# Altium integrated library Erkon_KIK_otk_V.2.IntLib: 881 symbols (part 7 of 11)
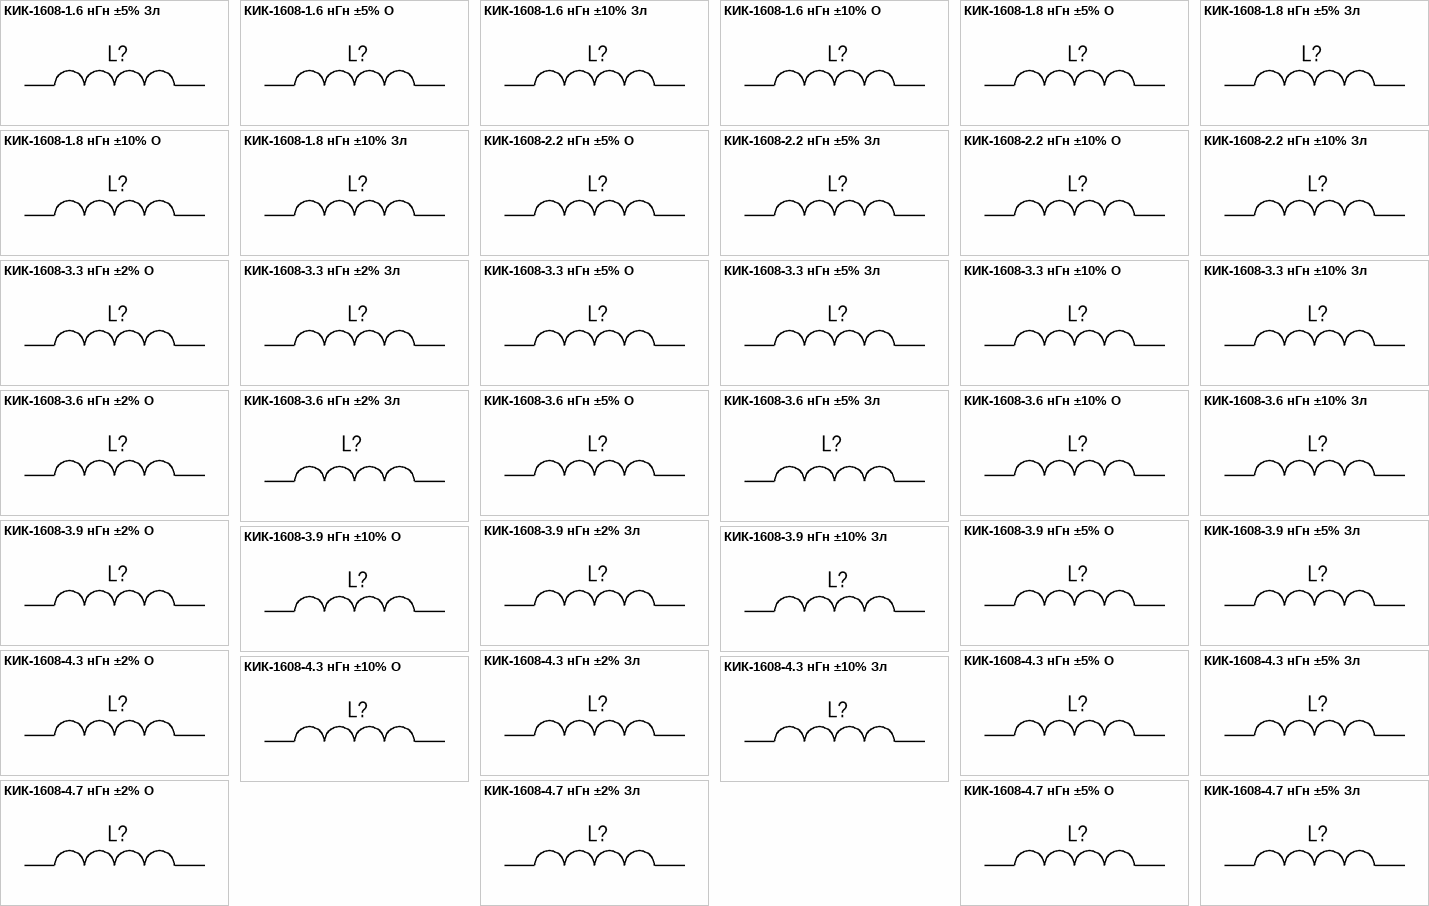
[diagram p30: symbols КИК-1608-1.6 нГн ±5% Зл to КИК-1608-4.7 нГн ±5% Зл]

## КИК-1608-3.9 нГн ±2% Зл
designator L?, comment 3.9 нГн ±2%  (value not drawn)
Катушка индуктивности с керамическим сердечником и золотым покрытием контактных площадок; Номиналиная индуктивность: 3.9 нГн; Добротность, не менее: 16; Резонансная частота, не менее: 6.90 ГГц; Сопротивление обмотки постоянноми току, не более: 0.080 Ом; Допустимый ток обмотки: 700 мА; Диапазон рабочих температур: от -60 до +125 ℃; Упаковка: Катушка и лента; Типоразмер: 1608 (0603); Технология монтажа: SMT; Изготовитель: АО "НПО "ЭРКОН"
footprint КИК-1608_Зл (Катушка индуктивности с керамическим сердечником  типоразмер 1005(0402))
pins: 1, 2

## КИК-1608-3.9 нГн ±5% O
designator L?, comment 3.9 нГн ±5%  (value not drawn)
Катушка индуктивности с керамическим сердечником и  финишным покрытием контактных площадок оловом; Номиналиная индуктивность: 3.9 нГн; Добротность, не менее: 16; Резонансная частота, не менее: 6.90 ГГц; Сопротивление обмотки постоянноми току, не более: 0.080 Ом; Допустимый ток обмотки: 700 мА; Диапазон рабочих температур: от -60 до +125 ℃; Упаковка: Катушка и лента; Типоразмер: 1608 (0603); Технология монтажа: SMT; Изготовитель: АО "НПО "ЭРКОН"
footprint КИК-1608_О (Катушка индуктивности с керамическим сердечником  типоразмер 1005(0402))
pins: 1, 2

## КИК-1608-3.9 нГн ±5% Зл
designator L?, comment 3.9 нГн ±5%  (value not drawn)
Катушка индуктивности с керамическим сердечником и золотым покрытием контактных площадок; Номиналиная индуктивность: 3.9 нГн; Добротность, не менее: 16; Резонансная частота, не менее: 6.90 ГГц; Сопротивление обмотки постоянноми току, не более: 0.080 Ом; Допустимый ток обмотки: 700 мА; Диапазон рабочих температур: от -60 до +125 ℃; Упаковка: Катушка и лента; Типоразмер: 1608 (0603); Технология монтажа: SMT; Изготовитель: АО "НПО "ЭРКОН"
footprint КИК-1608_Зл (Катушка индуктивности с керамическим сердечником  типоразмер 1005(0402))
pins: 1, 2

## КИК-1608-3.9 нГн ±10% O
designator L?, comment 3.9 нГн ±10%  (value not drawn)
Катушка индуктивности с керамическим сердечником и  финишным покрытием контактных площадок оловом; Номиналиная индуктивность: 3.9 нГн; Добротность, не менее: 16; Резонансная частота, не менее: 6.90 ГГц; Сопротивление обмотки постоянноми току, не более: 0.080 Ом; Допустимый ток обмотки: 700 мА; Диапазон рабочих температур: от -60 до +125 ℃; Упаковка: Катушка и лента; Типоразмер: 1608 (0603); Технология монтажа: SMT; Изготовитель: АО "НПО "ЭРКОН"
footprint КИК-1608_О (Катушка индуктивности с керамическим сердечником  типоразмер 1005(0402))
pins: 1, 2

## КИК-1608-3.9 нГн ±10% Зл
designator L?, comment 3.9 нГн ±10%  (value not drawn)
Катушка индуктивности с керамическим сердечником и золотым покрытием контактных площадок; Номиналиная индуктивность: 3.9 нГн; Добротность, не менее: 16; Резонансная частота, не менее: 6.90 ГГц; Сопротивление обмотки постоянноми току, не более: 0.080 Ом; Допустимый ток обмотки: 700 мА; Диапазон рабочих температур: от -60 до +125 ℃; Упаковка: Катушка и лента; Типоразмер: 1608 (0603); Технология монтажа: SMT; Изготовитель: АО "НПО "ЭРКОН"
footprint КИК-1608_Зл (Катушка индуктивности с керамическим сердечником  типоразмер 1005(0402))
pins: 1, 2

## КИК-1608-4.3 нГн ±2% O
designator L?, comment 4.3 нГн ±2%  (value not drawn)
Катушка индуктивности с керамическим сердечником и  финишным покрытием контактных площадок оловом; Номиналиная индуктивность: 4.3 нГн; Допускаемое отклонение индуктивности: ±5%; Добротность, не менее: 16; Резонансная частота, не менее: 5.90 ГГц; Сопротивление обмотки постоянноми току, не более: 0.080 Ом; Допустимый ток обмотки: 700 мА; Диапазон рабочих температур: от -60 до +125 ℃; Упаковка: Катушка и лента; Типоразмер: 1608 (0603); Технология монтажа: SMT; Изготовитель: АО "НПО "ЭРКОН"
footprint КИК-1608_О (Катушка индуктивности с керамическим сердечником  типоразмер 1005(0402))
pins: 1, 2

## КИК-1608-4.3 нГн ±2% Зл
designator L?, comment 4.3 нГн ±2%  (value not drawn)
Катушка индуктивности с керамическим сердечником и золотым покрытием контактных площадок; Номиналиная индуктивность: 4.3 нГн; Допускаемое отклонение индуктивности: ±5%; Добротность, не менее: 16; Резонансная частота, не менее: 5.90 ГГц; Сопротивление обмотки постоянноми току, не более: 0.080 Ом; Допустимый ток обмотки: 700 мА; Диапазон рабочих температур: от -60 до +125 ℃; Упаковка: Катушка и лента; Типоразмер: 1608 (0603); Технология монтажа: SMT; Изготовитель: АО "НПО "ЭРКОН"
footprint КИК-1608_Зл (Катушка индуктивности с керамическим сердечником  типоразмер 1005(0402))
pins: 1, 2

## КИК-1608-4.3 нГн ±5% O
designator L?, comment 4.3 нГн ±5%  (value not drawn)
Катушка индуктивности с керамическим сердечником и  финишным покрытием контактных площадок оловом; Номиналиная индуктивность: 4.3 нГн; Добротность, не менее: 16; Резонансная частота, не менее: 5.90 ГГц; Сопротивление обмотки постоянноми току, не более: 0.080 Ом; Допустимый ток обмотки: 700 мА; Диапазон рабочих температур: от -60 до +125 ℃; Упаковка: Катушка и лента; Типоразмер: 1608 (0603); Технология монтажа: SMT; Изготовитель: АО "НПО "ЭРКОН"
footprint КИК-1608_О (Катушка индуктивности с керамическим сердечником  типоразмер 1005(0402))
pins: 1, 2

## КИК-1608-4.3 нГн ±5% Зл
designator L?, comment 4.3 нГн ±5%  (value not drawn)
Катушка индуктивности с керамическим сердечником и золотым покрытием контактных площадок; Номиналиная индуктивность: 4.3 нГн; Добротность, не менее: 16; Резонансная частота, не менее: 5.90 ГГц; Сопротивление обмотки постоянноми току, не более: 0.080 Ом; Допустимый ток обмотки: 700 мА; Диапазон рабочих температур: от -60 до +125 ℃; Упаковка: Катушка и лента; Типоразмер: 1608 (0603); Технология монтажа: SMT; Изготовитель: АО "НПО "ЭРКОН"
footprint КИК-1608_Зл (Катушка индуктивности с керамическим сердечником  типоразмер 1005(0402))
pins: 1, 2

## КИК-1608-4.3 нГн ±10% O
designator L?, comment 4.3 нГн ±10%  (value not drawn)
Катушка индуктивности с керамическим сердечником и  финишным покрытием контактных площадок оловом; Номиналиная индуктивность: 4.3 нГн; Добротность, не менее: 16; Резонансная частота, не менее: 5.90 ГГц; Сопротивление обмотки постоянноми току, не более: 0.080 Ом; Допустимый ток обмотки: 700 мА; Диапазон рабочих температур: от -60 до +125 ℃; Упаковка: Катушка и лента; Типоразмер: 1608 (0603); Технология монтажа: SMT; Изготовитель: АО "НПО "ЭРКОН"
footprint КИК-1608_О (Катушка индуктивности с керамическим сердечником  типоразмер 1005(0402))
pins: 1, 2

## КИК-1608-4.3 нГн ±10% Зл
designator L?, comment 4.3 нГн ±10%  (value not drawn)
Катушка индуктивности с керамическим сердечником и золотым покрытием контактных площадок; Номиналиная индуктивность: 4.3 нГн; Добротность, не менее: 16; Резонансная частота, не менее: 5.90 ГГц; Сопротивление обмотки постоянноми току, не более: 0.080 Ом; Допустимый ток обмотки: 700 мА; Диапазон рабочих температур: от -60 до +125 ℃; Упаковка: Катушка и лента; Типоразмер: 1608 (0603); Технология монтажа: SMT; Изготовитель: АО "НПО "ЭРКОН"
footprint КИК-1608_Зл (Катушка индуктивности с керамическим сердечником  типоразмер 1005(0402))
pins: 1, 2

## КИК-1608-4.7 нГн ±2% O
designator L?, comment 4.7 нГн ±2%  (value not drawn)
Катушка индуктивности с керамическим сердечником и  финишным покрытием контактных площадок оловом; Номиналиная индуктивность: 4.7 нГн; Добротность, не менее: 16; Резонансная частота, не менее: 5.80 ГГц; Сопротивление обмотки постоянноми току, не более: 0.116 Ом; Допустимый ток обмотки: 700 мА; Диапазон рабочих температур: от -60 до +125 ℃; Упаковка: Катушка и лента; Типоразмер: 1608 (0603); Технология монтажа: SMT; Изготовитель: АО "НПО "ЭРКОН"
footprint КИК-1608_О (Катушка индуктивности с керамическим сердечником  типоразмер 1005(0402))
pins: 1, 2

## КИК-1608-4.7 нГн ±2% Зл
designator L?, comment 4.7 нГн ±2%  (value not drawn)
Катушка индуктивности с керамическим сердечником и золотым покрытием контактных площадок; Номиналиная индуктивность: 4.7 нГн; Добротность, не менее: 16; Резонансная частота, не менее: 5.80 ГГц; Сопротивление обмотки постоянноми току, не более: 0.116 Ом; Допустимый ток обмотки: 700 мА; Диапазон рабочих температур: от -60 до +125 ℃; Упаковка: Катушка и лента; Типоразмер: 1608 (0603); Технология монтажа: SMT; Изготовитель: АО "НПО "ЭРКОН"
footprint КИК-1608_Зл (Катушка индуктивности с керамическим сердечником  типоразмер 1005(0402))
pins: 1, 2

## КИК-1608-4.7 нГн ±5% O
designator L?, comment 4.7 нГн ±5%  (value not drawn)
Катушка индуктивности с керамическим сердечником и  финишным покрытием контактных площадок оловом; Номиналиная индуктивность: 4.7 нГн; Добротность, не менее: 16; Резонансная частота, не менее: 5.80 ГГц; Сопротивление обмотки постоянноми току, не более: 0.116 Ом; Допустимый ток обмотки: 700 мА; Диапазон рабочих температур: от -60 до +125 ℃; Упаковка: Катушка и лента; Типоразмер: 1608 (0603); Технология монтажа: SMT; Изготовитель: АО "НПО "ЭРКОН"
footprint КИК-1608_О (Катушка индуктивности с керамическим сердечником  типоразмер 1005(0402))
pins: 1, 2

## КИК-1608-4.7 нГн ±5% Зл
designator L?, comment 4.7 нГн ±5%  (value not drawn)
Катушка индуктивности с керамическим сердечником и золотым покрытием контактных площадок; Номиналиная индуктивность: 4.7 нГн; Добротность, не менее: 16; Резонансная частота, не менее: 5.80 ГГц; Сопротивление обмотки постоянноми току, не более: 0.116 Ом; Допустимый ток обмотки: 700 мА; Диапазон рабочих температур: от -60 до +125 ℃; Упаковка: Катушка и лента; Типоразмер: 1608 (0603); Технология монтажа: SMT; Изготовитель: АО "НПО "ЭРКОН"
footprint КИК-1608_Зл (Катушка индуктивности с керамическим сердечником  типоразмер 1005(0402))
pins: 1, 2

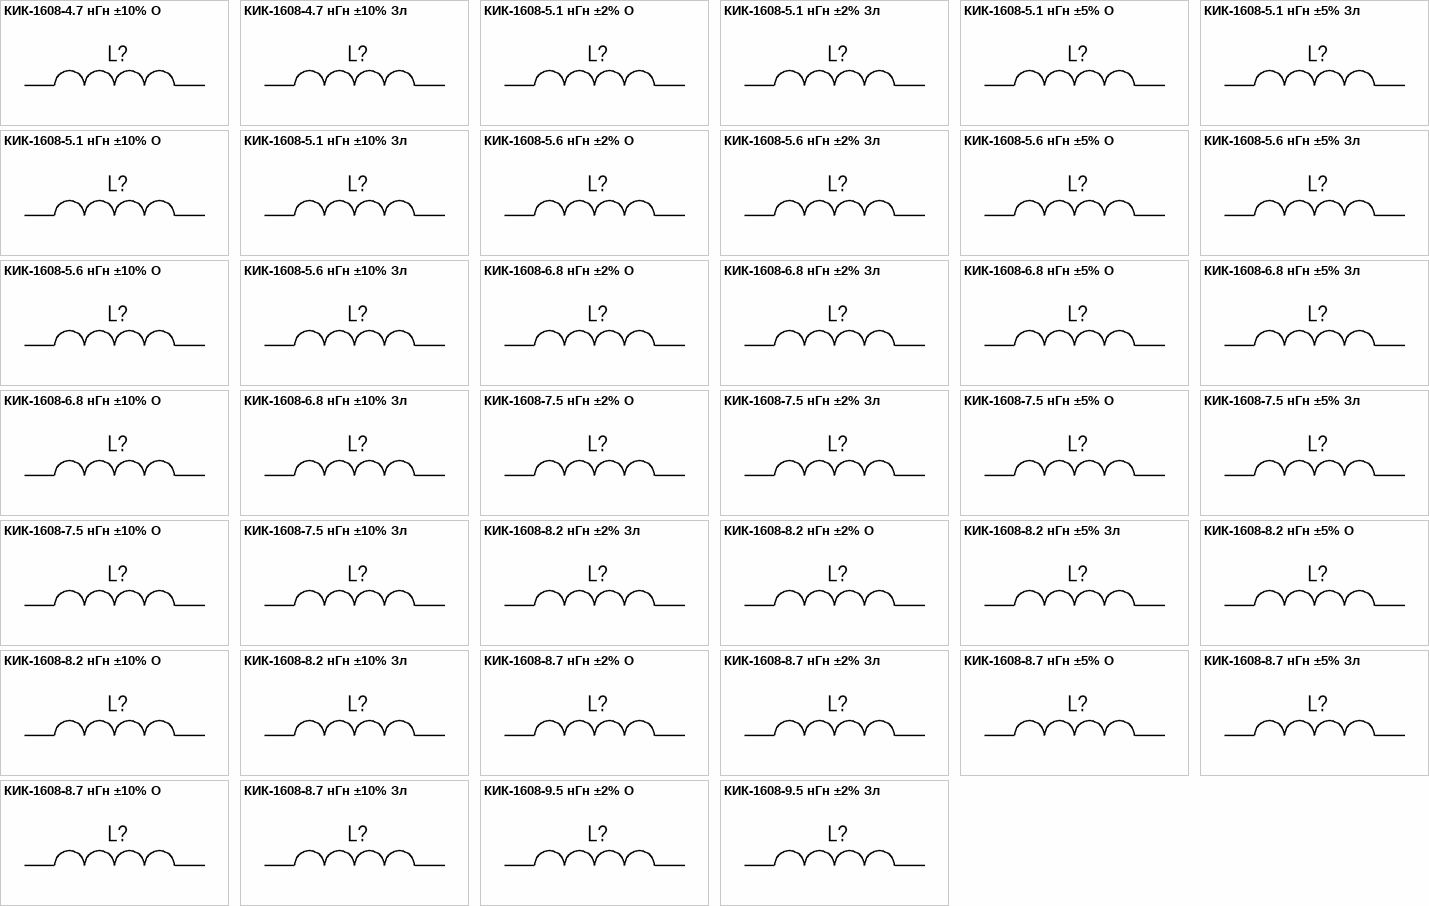
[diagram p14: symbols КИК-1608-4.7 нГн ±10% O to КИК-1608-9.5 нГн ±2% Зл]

## КИК-1608-4.7 нГн ±10% O
designator L?, comment 4.7 нГн ±10%  (value not drawn)
Катушка индуктивности с керамическим сердечником и  финишным покрытием контактных площадок оловом; Номиналиная индуктивность: 4.7 нГн; Добротность, не менее: 16; Резонансная частота, не менее: 5.80 ГГц; Сопротивление обмотки постоянноми току, не более: 0.116 Ом; Допустимый ток обмотки: 700 мА; Диапазон рабочих температур: от -60 до +125 ℃; Упаковка: Катушка и лента; Типоразмер: 1608 (0603); Технология монтажа: SMT; Изготовитель: АО "НПО "ЭРКОН"
footprint КИК-1608_О (Катушка индуктивности с керамическим сердечником  типоразмер 1005(0402))
pins: 1, 2

## КИК-1608-4.7 нГн ±10% Зл
designator L?, comment 4.7 нГн ±10%  (value not drawn)
Катушка индуктивности с керамическим сердечником и золотым покрытием контактных площадок; Номиналиная индуктивность: 4.7 нГн; Добротность, не менее: 16; Резонансная частота, не менее: 5.80 ГГц; Сопротивление обмотки постоянноми току, не более: 0.116 Ом; Допустимый ток обмотки: 700 мА; Диапазон рабочих температур: от -60 до +125 ℃; Упаковка: Катушка и лента; Типоразмер: 1608 (0603); Технология монтажа: SMT; Изготовитель: АО "НПО "ЭРКОН"
footprint КИК-1608_Зл (Катушка индуктивности с керамическим сердечником  типоразмер 1005(0402))
pins: 1, 2

## КИК-1608-5.1 нГн ±2% O
designator L?, comment 5.1 нГн ±2%  (value not drawn)
Катушка индуктивности с керамическим сердечником и  финишным покрытием контактных площадок оловом; Номиналиная индуктивность: 5.1 нГн; Добротность, не менее: 16; Резонансная частота, не менее: 5.70 ГГц; Сопротивление обмотки постоянноми току, не более: 0.140 Ом; Допустимый ток обмотки: 700 мА; Диапазон рабочих температур: от -60 до +125 ℃; Упаковка: Катушка и лента; Типоразмер: 1608 (0603); Технология монтажа: SMT; Изготовитель: АО "НПО "ЭРКОН"
footprint КИК-1608_О (Катушка индуктивности с керамическим сердечником  типоразмер 1005(0402))
pins: 1, 2

## КИК-1608-5.1 нГн ±2% Зл
designator L?, comment 5.1 нГн ±2%  (value not drawn)
Катушка индуктивности с керамическим сердечником и золотым покрытием контактных площадок; Номиналиная индуктивность: 5.1 нГн; Добротность, не менее: 16; Резонансная частота, не менее: 5.70 ГГц; Сопротивление обмотки постоянноми току, не более: 0.140 Ом; Допустимый ток обмотки: 700 мА; Диапазон рабочих температур: от -60 до +125 ℃; Упаковка: Катушка и лента; Типоразмер: 1608 (0603); Технология монтажа: SMT; Изготовитель: АО "НПО "ЭРКОН"
footprint КИК-1608_Зл (Катушка индуктивности с керамическим сердечником  типоразмер 1005(0402))
pins: 1, 2

## КИК-1608-5.1 нГн ±5% O
designator L?, comment 5.1 нГн ±5%  (value not drawn)
Катушка индуктивности с керамическим сердечником и  финишным покрытием контактных площадок оловом; Номиналиная индуктивность: 5.1 нГн; Добротность, не менее: 16; Резонансная частота, не менее: 5.70 ГГц; Сопротивление обмотки постоянноми току, не более: 0.140 Ом; Допустимый ток обмотки: 700 мА; Диапазон рабочих температур: от -60 до +125 ℃; Упаковка: Катушка и лента; Типоразмер: 1608 (0603); Технология монтажа: SMT; Изготовитель: АО "НПО "ЭРКОН"
footprint КИК-1608_О (Катушка индуктивности с керамическим сердечником  типоразмер 1005(0402))
pins: 1, 2

## КИК-1608-5.1 нГн ±5% Зл
designator L?, comment 5.1 нГн ±5%  (value not drawn)
Катушка индуктивности с керамическим сердечником и золотым покрытием контактных площадок; Номиналиная индуктивность: 5.1 нГн; Добротность, не менее: 16; Резонансная частота, не менее: 5.70 ГГц; Сопротивление обмотки постоянноми току, не более: 0.140 Ом; Допустимый ток обмотки: 700 мА; Диапазон рабочих температур: от -60 до +125 ℃; Упаковка: Катушка и лента; Типоразмер: 1608 (0603); Технология монтажа: SMT; Изготовитель: АО "НПО "ЭРКОН"
footprint КИК-1608_Зл (Катушка индуктивности с керамическим сердечником  типоразмер 1005(0402))
pins: 1, 2

## КИК-1608-5.1 нГн ±10% O
designator L?, comment 5.1 нГн ±10%  (value not drawn)
Катушка индуктивности с керамическим сердечником и  финишным покрытием контактных площадок оловом; Номиналиная индуктивность: 5.1 нГн; Добротность, не менее: 16; Резонансная частота, не менее: 5.70 ГГц; Сопротивление обмотки постоянноми току, не более: 0.140 Ом; Допустимый ток обмотки: 700 мА; Диапазон рабочих температур: от -60 до +125 ℃; Упаковка: Катушка и лента; Типоразмер: 1608 (0603); Технология монтажа: SMT; Изготовитель: АО "НПО "ЭРКОН"
footprint КИК-1608_О (Катушка индуктивности с керамическим сердечником  типоразмер 1005(0402))
pins: 1, 2

## КИК-1608-5.1 нГн ±10% Зл
designator L?, comment 5.1 нГн ±10%  (value not drawn)
Катушка индуктивности с керамическим сердечником и золотым покрытием контактных площадок; Номиналиная индуктивность: 5.1 нГн; Добротность, не менее: 16; Резонансная частота, не менее: 5.70 ГГц; Сопротивление обмотки постоянноми току, не более: 0.140 Ом; Допустимый ток обмотки: 700 мА; Диапазон рабочих температур: от -60 до +125 ℃; Упаковка: Катушка и лента; Типоразмер: 1608 (0603); Технология монтажа: SMT; Изготовитель: АО "НПО "ЭРКОН"
footprint КИК-1608_Зл (Катушка индуктивности с керамическим сердечником  типоразмер 1005(0402))
pins: 1, 2

## КИК-1608-5.6 нГн ±2% O
designator L?, comment 5.6 нГн ±2%  (value not drawn)
Катушка индуктивности с керамическим сердечником и  финишным покрытием контактных площадок оловом; Номиналиная индуктивность: 5.6 нГн; Добротность, не менее: 25; Резонансная частота, не менее: 4.76 ГГц; Сопротивление обмотки постоянноми току, не более: 0.145 Ом; Допустимый ток обмотки: 700 мА; Диапазон рабочих температур: от -60 до +125 ℃; Упаковка: Катушка и лента; Типоразмер: 1608 (0603); Технология монтажа: SMT; Изготовитель: АО "НПО "ЭРКОН"
footprint КИК-1608_О (Катушка индуктивности с керамическим сердечником  типоразмер 1005(0402))
pins: 1, 2

## КИК-1608-5.6 нГн ±2% Зл
designator L?, comment 5.6 нГн ±2%  (value not drawn)
Катушка индуктивности с керамическим сердечником и золотым покрытием контактных площадок; Номиналиная индуктивность: 5.6 нГн; Добротность, не менее: 25; Резонансная частота, не менее: 4.76 ГГц; Сопротивление обмотки постоянноми току, не более: 0.145 Ом; Допустимый ток обмотки: 700 мА; Диапазон рабочих температур: от -60 до +125 ℃; Упаковка: Катушка и лента; Типоразмер: 1608 (0603); Технология монтажа: SMT; Изготовитель: АО "НПО "ЭРКОН"
footprint КИК-1608_Зл (Катушка индуктивности с керамическим сердечником  типоразмер 1005(0402))
pins: 1, 2

## КИК-1608-5.6 нГн ±5% O
designator L?, comment 5.6 нГн ±5%  (value not drawn)
Катушка индуктивности с керамическим сердечником и  финишным покрытием контактных площадок оловом; Номиналиная индуктивность: 5.6 нГн; Добротность, не менее: 25; Резонансная частота, не менее: 4.76 ГГц; Сопротивление обмотки постоянноми току, не более: 0.145 Ом; Допустимый ток обмотки: 700 мА; Диапазон рабочих температур: от -60 до +125 ℃; Упаковка: Катушка и лента; Типоразмер: 1608 (0603); Технология монтажа: SMT; Изготовитель: АО "НПО "ЭРКОН"
footprint КИК-1608_О (Катушка индуктивности с керамическим сердечником  типоразмер 1005(0402))
pins: 1, 2

## КИК-1608-5.6 нГн ±5% Зл
designator L?, comment 5.6 нГн ±5%  (value not drawn)
Катушка индуктивности с керамическим сердечником и золотым покрытием контактных площадок; Номиналиная индуктивность: 5.6 нГн; Добротность, не менее: 25; Резонансная частота, не менее: 4.76 ГГц; Сопротивление обмотки постоянноми току, не более: 0.145 Ом; Допустимый ток обмотки: 700 мА; Диапазон рабочих температур: от -60 до +125 ℃; Упаковка: Катушка и лента; Типоразмер: 1608 (0603); Технология монтажа: SMT; Изготовитель: АО "НПО "ЭРКОН"
footprint КИК-1608_Зл (Катушка индуктивности с керамическим сердечником  типоразмер 1005(0402))
pins: 1, 2

## КИК-1608-5.6 нГн ±10% O
designator L?, comment 5.6 нГн ±10%  (value not drawn)
Катушка индуктивности с керамическим сердечником и  финишным покрытием контактных площадок оловом; Номиналиная индуктивность: 5.6 нГн; Добротность, не менее: 25; Резонансная частота, не менее: 4.76 ГГц; Сопротивление обмотки постоянноми току, не более: 0.145 Ом; Допустимый ток обмотки: 700 мА; Диапазон рабочих температур: от -60 до +125 ℃; Упаковка: Катушка и лента; Типоразмер: 1608 (0603); Технология монтажа: SMT; Изготовитель: АО "НПО "ЭРКОН"
footprint КИК-1608_О (Катушка индуктивности с керамическим сердечником  типоразмер 1005(0402))
pins: 1, 2

## КИК-1608-5.6 нГн ±10% Зл
designator L?, comment 5.6 нГн ±10%  (value not drawn)
Катушка индуктивности с керамическим сердечником и золотым покрытием контактных площадок; Номиналиная индуктивность: 5.6 нГн; Добротность, не менее: 25; Резонансная частота, не менее: 4.76 ГГц; Сопротивление обмотки постоянноми току, не более: 0.145 Ом; Допустимый ток обмотки: 700 мА; Диапазон рабочих температур: от -60 до +125 ℃; Упаковка: Катушка и лента; Типоразмер: 1608 (0603); Технология монтажа: SMT; Изготовитель: АО "НПО "ЭРКОН"
footprint КИК-1608_Зл (Катушка индуктивности с керамическим сердечником  типоразмер 1005(0402))
pins: 1, 2

## КИК-1608-6.8 нГн ±2% O
designator L?, comment 6.8 нГн ±2%  (value not drawn)
Катушка индуктивности с керамическим сердечником и  финишным покрытием контактных площадок оловом; Номиналиная индуктивность: 6.8 нГн; Добротность, не менее: 25; Резонансная частота, не менее: 5.80 ГГц; Сопротивление обмотки постоянноми току, не более: 0.110 Ом; Допустимый ток обмотки: 700 мА; Диапазон рабочих температур: от -60 до +125 ℃; Упаковка: Катушка и лента; Типоразмер: 1608 (0603); Технология монтажа: SMT; Изготовитель: АО "НПО "ЭРКОН"
footprint КИК-1608_О (Катушка индуктивности с керамическим сердечником  типоразмер 1005(0402))
pins: 1, 2

## КИК-1608-6.8 нГн ±2% Зл
designator L?, comment 6.8 нГн ±2%  (value not drawn)
Катушка индуктивности с керамическим сердечником и золотым покрытием контактных площадок; Номиналиная индуктивность: 6.8 нГн; Добротность, не менее: 25; Резонансная частота, не менее: 5.80 ГГц; Сопротивление обмотки постоянноми току, не более: 0.110 Ом; Допустимый ток обмотки: 700 мА; Диапазон рабочих температур: от -60 до +125 ℃; Упаковка: Катушка и лента; Типоразмер: 1608 (0603); Технология монтажа: SMT; Изготовитель: АО "НПО "ЭРКОН"
footprint КИК-1608_Зл (Катушка индуктивности с керамическим сердечником  типоразмер 1005(0402))
pins: 1, 2

## КИК-1608-6.8 нГн ±5% O
designator L?, comment 6.8 нГн ±5%  (value not drawn)
Катушка индуктивности с керамическим сердечником и  финишным покрытием контактных площадок оловом; Номиналиная индуктивность: 6.8 нГн; Добротность, не менее: 25; Резонансная частота, не менее: 5.80 ГГц; Сопротивление обмотки постоянноми току, не более: 0.110 Ом; Допустимый ток обмотки: 700 мА; Диапазон рабочих температур: от -60 до +125 ℃; Упаковка: Катушка и лента; Типоразмер: 1608 (0603); Технология монтажа: SMT; Изготовитель: АО "НПО "ЭРКОН"
footprint КИК-1608_О (Катушка индуктивности с керамическим сердечником  типоразмер 1005(0402))
pins: 1, 2

## КИК-1608-6.8 нГн ±5% Зл
designator L?, comment 6.8 нГн ±5%  (value not drawn)
Катушка индуктивности с керамическим сердечником и золотым покрытием контактных площадок; Номиналиная индуктивность: 6.8 нГн; Добротность, не менее: 25; Резонансная частота, не менее: 5.80 ГГц; Сопротивление обмотки постоянноми току, не более: 0.110 Ом; Допустимый ток обмотки: 700 мА; Диапазон рабочих температур: от -60 до +125 ℃; Упаковка: Катушка и лента; Типоразмер: 1608 (0603); Технология монтажа: SMT; Изготовитель: АО "НПО "ЭРКОН"
footprint КИК-1608_Зл (Катушка индуктивности с керамическим сердечником  типоразмер 1005(0402))
pins: 1, 2

## КИК-1608-6.8 нГн ±10% O
designator L?, comment 6.8 нГн ±10%  (value not drawn)
Катушка индуктивности с керамическим сердечником и  финишным покрытием контактных площадок оловом; Номиналиная индуктивность: 6.8 нГн; Добротность, не менее: 25; Резонансная частота, не менее: 5.80 ГГц; Сопротивление обмотки постоянноми току, не более: 0.110 Ом; Допустимый ток обмотки: 700 мА; Диапазон рабочих температур: от -60 до +125 ℃; Упаковка: Катушка и лента; Типоразмер: 1608 (0603); Технология монтажа: SMT; Изготовитель: АО "НПО "ЭРКОН"
footprint КИК-1608_О (Катушка индуктивности с керамическим сердечником  типоразмер 1005(0402))
pins: 1, 2

## КИК-1608-6.8 нГн ±10% Зл
designator L?, comment 6.8 нГн ±10%  (value not drawn)
Катушка индуктивности с керамическим сердечником и золотым покрытием контактных площадок; Номиналиная индуктивность: 6.8 нГн; Добротность, не менее: 25; Резонансная частота, не менее: 5.80 ГГц; Сопротивление обмотки постоянноми току, не более: 0.110 Ом; Допустимый ток обмотки: 700 мА; Диапазон рабочих температур: от -60 до +125 ℃; Упаковка: Катушка и лента; Типоразмер: 1608 (0603); Технология монтажа: SMT; Изготовитель: АО "НПО "ЭРКОН"
footprint КИК-1608_Зл (Катушка индуктивности с керамическим сердечником  типоразмер 1005(0402))
pins: 1, 2

## КИК-1608-7.5 нГн ±2% O
designator L?, comment 7.5 нГн ±2%  (value not drawn)
Катушка индуктивности с керамическим сердечником и  финишным покрытием контактных площадок оловом; Номиналиная индуктивность: 7.5 нГн; Добротность, не менее: 25; Резонансная частота, не менее: 4.80 ГГц; Сопротивление обмотки постоянноми току, не более: 0.110 Ом; Допустимый ток обмотки: 700 мА; Диапазон рабочих температур: от -60 до +125 ℃; Упаковка: Катушка и лента; Типоразмер: 1608 (0603); Технология монтажа: SMT; Изготовитель: АО "НПО "ЭРКОН"
footprint КИК-1608_О (Катушка индуктивности с керамическим сердечником  типоразмер 1005(0402))
pins: 1, 2

## КИК-1608-7.5 нГн ±2% Зл
designator L?, comment 7.5 нГн ±2%  (value not drawn)
Катушка индуктивности с керамическим сердечником и  золотым покрытием контактных площадок; Номиналиная индуктивность: 7.5 нГн; Добротность, не менее: 25; Резонансная частота, не менее: 4.80 ГГц; Сопротивление обмотки постоянноми току, не более: 0.110 Ом; Допустимый ток обмотки: 700 мА; Диапазон рабочих температур: от -60 до +125 ℃; Упаковка: Катушка и лента; Типоразмер: 1608 (0603); Технология монтажа: SMT; Изготовитель: АО "НПО "ЭРКОН"
footprint КИК-1608_О (Катушка индуктивности с керамическим сердечником  типоразмер 1005(0402))
pins: 1, 2

## КИК-1608-7.5 нГн ±5% O
designator L?, comment 7.5 нГн ±5%  (value not drawn)
Катушка индуктивности с керамическим сердечником и  финишным покрытием контактных площадок оловом; Номиналиная индуктивность: 7.5 нГн; Добротность, не менее: 25; Резонансная частота, не менее: 4.80 ГГц; Сопротивление обмотки постоянноми току, не более: 0.110 Ом; Допустимый ток обмотки: 700 мА; Диапазон рабочих температур: от -60 до +125 ℃; Упаковка: Катушка и лента; Типоразмер: 1608 (0603); Технология монтажа: SMT; Изготовитель: АО "НПО "ЭРКОН"
footprint КИК-1608_О (Катушка индуктивности с керамическим сердечником  типоразмер 1005(0402))
pins: 1, 2

## КИК-1608-7.5 нГн ±5% Зл
designator L?, comment 7.5 нГн ±5%  (value not drawn)
Катушка индуктивности с керамическим сердечником и  золотым покрытием контактных площадок; Номиналиная индуктивность: 7.5 нГн; Добротность, не менее: 25; Резонансная частота, не менее: 4.80 ГГц; Сопротивление обмотки постоянноми току, не более: 0.110 Ом; Допустимый ток обмотки: 700 мА; Диапазон рабочих температур: от -60 до +125 ℃; Упаковка: Катушка и лента; Типоразмер: 1608 (0603); Технология монтажа: SMT; Изготовитель: АО "НПО "ЭРКОН"
footprint КИК-1608_О (Катушка индуктивности с керамическим сердечником  типоразмер 1005(0402))
pins: 1, 2

## КИК-1608-7.5 нГн ±10% O
designator L?, comment 7.5 нГн ±10%  (value not drawn)
Катушка индуктивности с керамическим сердечником и  финишным покрытием контактных площадок оловом; Номиналиная индуктивность: 7.5 нГн; Добротность, не менее: 25; Резонансная частота, не менее: 4.80 ГГц; Сопротивление обмотки постоянноми току, не более: 0.110 Ом; Допустимый ток обмотки: 700 мА; Диапазон рабочих температур: от -60 до +125 ℃; Упаковка: Катушка и лента; Типоразмер: 1608 (0603); Технология монтажа: SMT; Изготовитель: АО "НПО "ЭРКОН"
footprint КИК-1608_О (Катушка индуктивности с керамическим сердечником  типоразмер 1005(0402))
pins: 1, 2

## КИК-1608-7.5 нГн ±10% Зл
designator L?, comment 7.5 нГн ±5%  (value not drawn)
Катушка индуктивности с керамическим сердечником и золотым покрытием контактных площадок; Номиналиная индуктивность: 7.5 нГн; Допускаемое отклонение индуктивности: ±10%; Добротность, не менее: 25; Резонансная частота, не менее: 4.80 ГГц; Сопротивление обмотки постоянноми току, не более: 0.110 Ом; Допустимый ток обмотки: 700 мА; Диапазон рабочих температур: от -60 до +125 ℃; Упаковка: Катушка и лента; Типоразмер: 1608 (0603); Технология монтажа: SMT; Изготовитель: АО "НПО "ЭРКОН"
footprint КИК-1608_Зл (Катушка индуктивности с керамическим сердечником  типоразмер 1005(0402))
pins: 1, 2

## КИК-1608-8.2 нГн ±2% Зл
designator L?, comment 8.2 нГн ±2%  (value not drawn)
Катушка индуктивности с керамическим сердечником и золотым покрытием контактных площадок; Номиналиная индуктивность: 8.2 нГн; Добротность, не менее: 30; Резонансная частота, не менее: 4.20 ГГц; Сопротивление обмотки постоянноми току, не более: 0.115 Ом; Допустимый ток обмотки: 700 мА; Диапазон рабочих температур: от -60 до +125 ℃; Упаковка: Катушка и лента; Типоразмер: 1608 (0603); Технология монтажа: SMT; Изготовитель: АО "НПО "ЭРКОН"
footprint КИК-1608_Зл (Катушка индуктивности с керамическим сердечником  типоразмер 1005(0402))
pins: 1, 2

## КИК-1608-8.2 нГн ±2% О
designator L?, comment 8.2 нГн ±2%  (value not drawn)
Катушка индуктивности с керамическим сердечником и  финишным покрытием контактных площадок оловом; Номиналиная индуктивность: 8.2 нГн; Добротность, не менее: 30; Резонансная частота, не менее: 4.20 ГГц; Сопротивление обмотки постоянноми току, не более: 0.115 Ом; Допустимый ток обмотки: 700 мА; Диапазон рабочих температур: от -60 до +125 ℃; Упаковка: Катушка и лента; Типоразмер: 1608 (0603); Технология монтажа: SMT; Изготовитель: АО "НПО "ЭРКОН"
footprint КИК-1608_О (Катушка индуктивности с керамическим сердечником  типоразмер 1005(0402))
pins: 1, 2

## КИК-1608-8.2 нГн ±5% Зл
designator L?, comment 8.2 нГн ±5%  (value not drawn)
Катушка индуктивности с керамическим сердечником и золотым покрытием контактных площадок; Номиналиная индуктивность: 8.2 нГн; Добротность, не менее: 30; Резонансная частота, не менее: 4.20 ГГц; Сопротивление обмотки постоянноми току, не более: 0.115 Ом; Допустимый ток обмотки: 700 мА; Диапазон рабочих температур: от -60 до +125 ℃; Упаковка: Катушка и лента; Типоразмер: 1608 (0603); Технология монтажа: SMT; Изготовитель: АО "НПО "ЭРКОН"
footprint КИК-1608_Зл (Катушка индуктивности с керамическим сердечником  типоразмер 1005(0402))
pins: 1, 2

## КИК-1608-8.2 нГн ±5% О
designator L?, comment 8.2 нГн ±5%  (value not drawn)
Катушка индуктивности с керамическим сердечником и  финишным покрытием контактных площадок оловом; Номиналиная индуктивность: 8.2 нГн; Добротность, не менее: 30; Резонансная частота, не менее: 4.20 ГГц; Сопротивление обмотки постоянноми току, не более: 0.115 Ом; Допустимый ток обмотки: 700 мА; Диапазон рабочих температур: от -60 до +125 ℃; Упаковка: Катушка и лента; Типоразмер: 1608 (0603); Технология монтажа: SMT; Изготовитель: АО "НПО "ЭРКОН"
footprint КИК-1608_О (Катушка индуктивности с керамическим сердечником  типоразмер 1005(0402))
pins: 1, 2

## КИК-1608-8.2 нГн ±10% O
designator L?, comment 8.2 нГн ±10%  (value not drawn)
Катушка индуктивности с керамическим сердечником и  финишным покрытием контактных площадок оловом; Номиналиная индуктивность: 8.2 нГн; Добротность, не менее: 30; Резонансная частота, не менее: 4.20 ГГц; Сопротивление обмотки постоянноми току, не более: 0.115 Ом; Допустимый ток обмотки: 700 мА; Диапазон рабочих температур: от -60 до +125 ℃; Упаковка: Катушка и лента; Типоразмер: 1608 (0603); Технология монтажа: SMT; Изготовитель: АО "НПО "ЭРКОН"
footprint КИК-1608_О (Катушка индуктивности с керамическим сердечником  типоразмер 1005(0402))
pins: 1, 2

## КИК-1608-8.2 нГн ±10% Зл
designator L?, comment 8.2 нГн ±10%  (value not drawn)
Катушка индуктивности с керамическим сердечником и золотым покрытием контактных площадок; Номиналиная индуктивность: 8.2 нГн; Добротность, не менее: 30; Резонансная частота, не менее: 4.20 ГГц; Сопротивление обмотки постоянноми току, не более: 0.115 Ом; Допустимый ток обмотки: 700 мА; Диапазон рабочих температур: от -60 до +125 ℃; Упаковка: Катушка и лента; Типоразмер: 1608 (0603); Технология монтажа: SMT; Изготовитель: АО "НПО "ЭРКОН"
footprint КИК-1608_Зл (Катушка индуктивности с керамическим сердечником  типоразмер 1005(0402))
pins: 1, 2

## КИК-1608-8.7 нГн ±2% O
designator L?, comment 8.7 нГн ±2%  (value not drawn)
Катушка индуктивности с керамическим сердечником и  финишным покрытием контактных площадок оловом; Номиналиная индуктивность: 8.7 нГн; Добротность, не менее: 30; Резонансная частота, не менее: 4.60 ГГц; Сопротивление обмотки постоянноми току, не более: 0.110 Ом; Допустимый ток обмотки: 700 мА; Диапазон рабочих температур: от -60 до +125 ℃; Упаковка: Катушка и лента; Типоразмер: 1608 (0603); Технология монтажа: SMT; Изготовитель: АО "НПО "ЭРКОН"
footprint КИК-1608_О (Катушка индуктивности с керамическим сердечником  типоразмер 1005(0402))
pins: 1, 2

## КИК-1608-8.7 нГн ±2% Зл
designator L?, comment 8.7 нГн ±2%  (value not drawn)
Катушка индуктивности с керамическим сердечником и золотым покрытием контактных площадок; Номиналиная индуктивность: 8.7 нГн; Добротность, не менее: 30; Резонансная частота, не менее: 4.60 ГГц; Сопротивление обмотки постоянноми току, не более: 0.110 Ом; Допустимый ток обмотки: 700 мА; Диапазон рабочих температур: от -60 до +125 ℃; Упаковка: Катушка и лента; Типоразмер: 1608 (0603); Технология монтажа: SMT; Изготовитель: АО "НПО "ЭРКОН"
footprint КИК-1608_Зл (Катушка индуктивности с керамическим сердечником  типоразмер 1005(0402))
pins: 1, 2

## КИК-1608-8.7 нГн ±5% O
designator L?, comment 8.7 нГн ±5%  (value not drawn)
Катушка индуктивности с керамическим сердечником и  финишным покрытием контактных площадок оловом; Номиналиная индуктивность: 8.7 нГн; Добротность, не менее: 30; Резонансная частота, не менее: 4.60 ГГц; Сопротивление обмотки постоянноми току, не более: 0.110 Ом; Допустимый ток обмотки: 700 мА; Диапазон рабочих температур: от -60 до +125 ℃; Упаковка: Катушка и лента; Типоразмер: 1608 (0603); Технология монтажа: SMT; Изготовитель: АО "НПО "ЭРКОН"
footprint КИК-1608_О (Катушка индуктивности с керамическим сердечником  типоразмер 1005(0402))
pins: 1, 2

## КИК-1608-8.7 нГн ±5% Зл
designator L?, comment 8.7 нГн ±5%  (value not drawn)
Катушка индуктивности с керамическим сердечником и золотым покрытием контактных площадок; Номиналиная индуктивность: 8.7 нГн; Добротность, не менее: 30; Резонансная частота, не менее: 4.60 ГГц; Сопротивление обмотки постоянноми току, не более: 0.110 Ом; Допустимый ток обмотки: 700 мА; Диапазон рабочих температур: от -60 до +125 ℃; Упаковка: Катушка и лента; Типоразмер: 1608 (0603); Технология монтажа: SMT; Изготовитель: АО "НПО "ЭРКОН"
footprint КИК-1608_Зл (Катушка индуктивности с керамическим сердечником  типоразмер 1005(0402))
pins: 1, 2

## КИК-1608-8.7 нГн ±10% O
designator L?, comment 8.7 нГн ±10%  (value not drawn)
Катушка индуктивности с керамическим сердечником и  финишным покрытием контактных площадок оловом; Номиналиная индуктивность: 8.7 нГн; Добротность, не менее: 30; Резонансная частота, не менее: 4.60 ГГц; Сопротивление обмотки постоянноми току, не более: 0.110 Ом; Допустимый ток обмотки: 700 мА; Диапазон рабочих температур: от -60 до +125 ℃; Упаковка: Катушка и лента; Типоразмер: 1608 (0603); Технология монтажа: SMT; Изготовитель: АО "НПО "ЭРКОН"
footprint КИК-1608_О (Катушка индуктивности с керамическим сердечником  типоразмер 1005(0402))
pins: 1, 2

## КИК-1608-8.7 нГн ±10% Зл
designator L?, comment 8.7 нГн ±10%  (value not drawn)
Катушка индуктивности с керамическим сердечником и золотым покрытием контактных площадок; Номиналиная индуктивность: 8.7 нГн; Добротность, не менее: 30; Резонансная частота, не менее: 4.60 ГГц; Сопротивление обмотки постоянноми току, не более: 0.110 Ом; Допустимый ток обмотки: 700 мА; Диапазон рабочих температур: от -60 до +125 ℃; Упаковка: Катушка и лента; Типоразмер: 1608 (0603); Технология монтажа: SMT; Изготовитель: АО "НПО "ЭРКОН"
footprint КИК-1608_Зл (Катушка индуктивности с керамическим сердечником  типоразмер 1005(0402))
pins: 1, 2

## КИК-1608-9.5 нГн ±2% O
designator L?, comment 9.5 нГн ±2%  (value not drawn)
Катушка индуктивности с керамическим сердечником и  финишным покрытием контактных площадок оловом; Номиналиная индуктивность: 9.5 нГн; Добротность, не менее: 30; Резонансная частота, не менее: 5.40 ГГц; Сопротивление обмотки постоянноми току, не более: 0.135 Ом; Допустимый ток обмотки: 700 мА; Диапазон рабочих температур: от -60 до +125 ℃; Упаковка: Катушка и лента; Типоразмер: 1608 (0603); Технология монтажа: SMT; Изготовитель: АО "НПО "ЭРКОН"
footprint КИК-1608_О (Катушка индуктивности с керамическим сердечником  типоразмер 1005(0402))
pins: 1, 2

## КИК-1608-9.5 нГн ±2% Зл
designator L?, comment 9.5 нГн ±2%  (value not drawn)
Катушка индуктивности с керамическим сердечником и золотым покрытием контактных площадок; Номиналиная индуктивность: 9.5 нГн; Добротность, не менее: 30; Резонансная частота, не менее: 5.40 ГГц; Сопротивление обмотки постоянноми току, не более: 0.135 Ом; Допустимый ток обмотки: 700 мА; Диапазон рабочих температур: от -60 до +125 ℃; Упаковка: Катушка и лента; Типоразмер: 1608 (0603); Технология монтажа: SMT; Изготовитель: АО "НПО "ЭРКОН"
footprint КИК-1608_Зл (Катушка индуктивности с керамическим сердечником  типоразмер 1005(0402))
pins: 1, 2

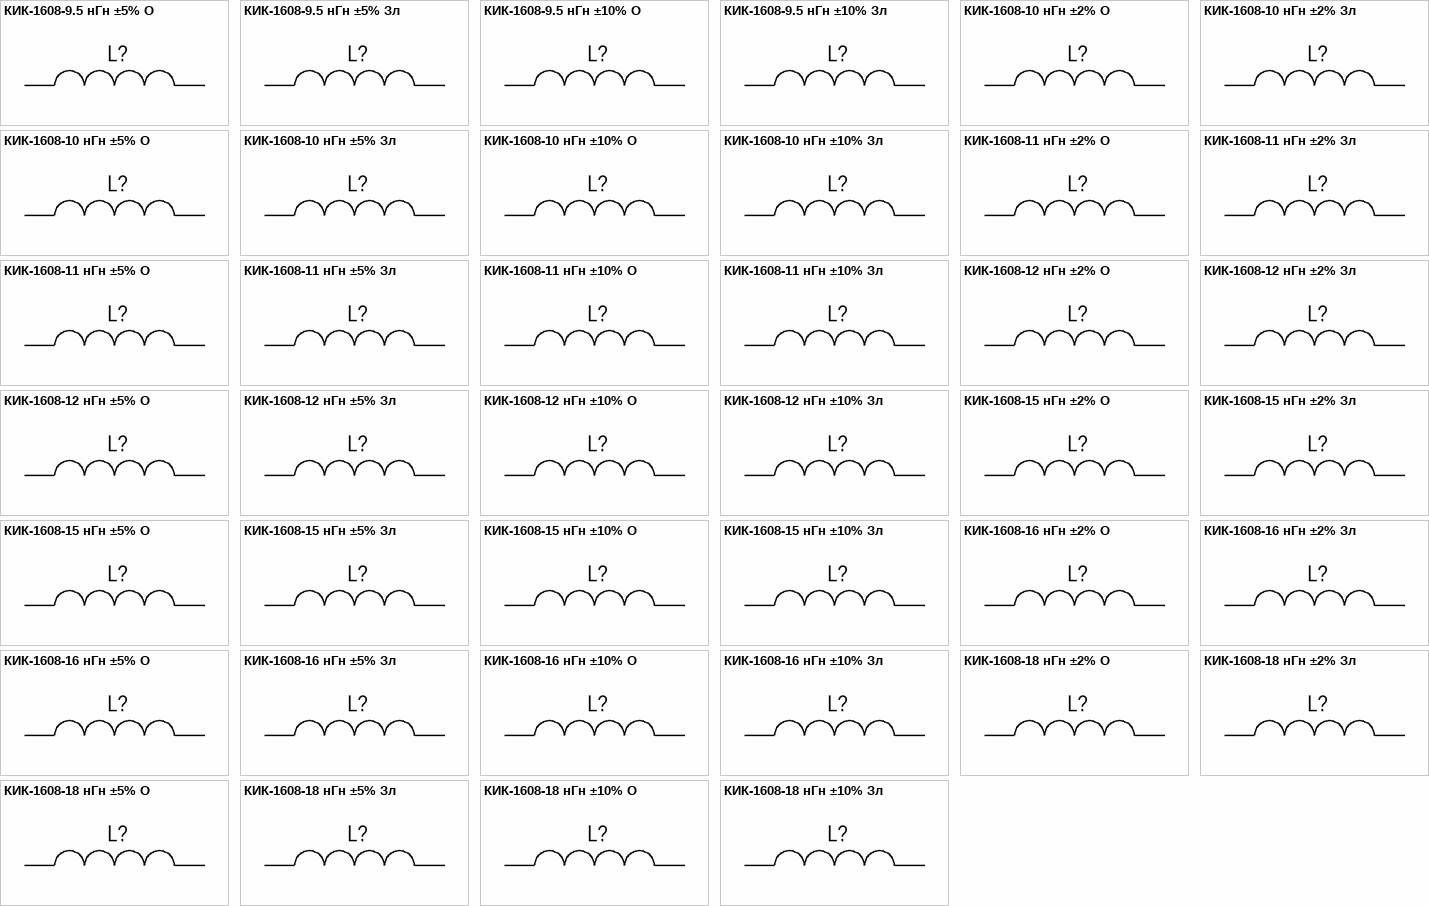
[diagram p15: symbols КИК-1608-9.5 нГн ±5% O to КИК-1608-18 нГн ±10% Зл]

## КИК-1608-9.5 нГн ±5% O
designator L?, comment 9.5 нГн ±5%  (value not drawn)
Катушка индуктивности с керамическим сердечником и  финишным покрытием контактных площадок оловом; Номиналиная индуктивность: 9.5 нГн; Добротность, не менее: 30; Резонансная частота, не менее: 5.40 ГГц; Сопротивление обмотки постоянноми току, не более: 0.135 Ом; Допустимый ток обмотки: 700 мА; Диапазон рабочих температур: от -60 до +125 ℃; Упаковка: Катушка и лента; Типоразмер: 1608 (0603); Технология монтажа: SMT; Изготовитель: АО "НПО "ЭРКОН"
footprint КИК-1608_О (Катушка индуктивности с керамическим сердечником  типоразмер 1005(0402))
pins: 1, 2

## КИК-1608-9.5 нГн ±5% Зл
designator L?, comment 9.5 нГн ±5%  (value not drawn)
Катушка индуктивности с керамическим сердечником и золотым покрытием контактных площадок; Номиналиная индуктивность: 9.5 нГн; Добротность, не менее: 30; Резонансная частота, не менее: 5.40 ГГц; Сопротивление обмотки постоянноми току, не более: 0.135 Ом; Допустимый ток обмотки: 700 мА; Диапазон рабочих температур: от -60 до +125 ℃; Упаковка: Катушка и лента; Типоразмер: 1608 (0603); Технология монтажа: SMT; Изготовитель: АО "НПО "ЭРКОН"
footprint КИК-1608_Зл (Катушка индуктивности с керамическим сердечником  типоразмер 1005(0402))
pins: 1, 2

## КИК-1608-9.5 нГн ±10% O
designator L?, comment 9.5 нГн ±10%  (value not drawn)
Катушка индуктивности с керамическим сердечником и  финишным покрытием контактных площадок оловом; Номиналиная индуктивность: 9.5 нГн; Добротность, не менее: 30; Резонансная частота, не менее: 5.40 ГГц; Сопротивление обмотки постоянноми току, не более: 0.135 Ом; Допустимый ток обмотки: 700 мА; Диапазон рабочих температур: от -60 до +125 ℃; Упаковка: Катушка и лента; Типоразмер: 1608 (0603); Технология монтажа: SMT; Изготовитель: АО "НПО "ЭРКОН"
footprint КИК-1608_О (Катушка индуктивности с керамическим сердечником  типоразмер 1005(0402))
pins: 1, 2

## КИК-1608-9.5 нГн ±10% Зл
designator L?, comment 9.5 нГн ±10%  (value not drawn)
Катушка индуктивности с керамическим сердечником и золотым покрытием контактных площадок; Номиналиная индуктивность: 9.5 нГн; Добротность, не менее: 30; Резонансная частота, не менее: 5.40 ГГц; Сопротивление обмотки постоянноми току, не более: 0.135 Ом; Допустимый ток обмотки: 700 мА; Диапазон рабочих температур: от -60 до +125 ℃; Упаковка: Катушка и лента; Типоразмер: 1608 (0603); Технология монтажа: SMT; Изготовитель: АО "НПО "ЭРКОН"
footprint КИК-1608_Зл (Катушка индуктивности с керамическим сердечником  типоразмер 1005(0402))
pins: 1, 2

## КИК-1608-10 нГн ±2% O
designator L?, comment 10 нГн ±2%  (value not drawn)
Катушка индуктивности с керамическим сердечником и  финишным покрытием контактных площадок оловом; Номиналиная индуктивность: 10 нГн; Добротность, не менее: 30; Резонансная частота, не менее: 4.80 ГГц; Сопротивление обмотки постоянноми току, не более: 0.130 Ом; Допустимый ток обмотки: 700 мА; Диапазон рабочих температур: от -60 до +125 ℃; Упаковка: Катушка и лента; Типоразмер: 1608 (0603); Технология монтажа: SMT; Изготовитель: АО "НПО "ЭРКОН"
footprint КИК-1608_О (Катушка индуктивности с керамическим сердечником  типоразмер 1005(0402))
pins: 1, 2

## КИК-1608-10 нГн ±2% Зл
designator L?, comment 10 нГн ±2%  (value not drawn)
Катушка индуктивности с керамическим сердечником и золотым покрытием контактных площадок; Номиналиная индуктивность: 10 нГн; Добротность, не менее: 30; Резонансная частота, не менее: 4.80 ГГц; Сопротивление обмотки постоянноми току, не более: 0.130 Ом; Допустимый ток обмотки: 700 мА; Диапазон рабочих температур: от -60 до +125 ℃; Упаковка: Катушка и лента; Типоразмер: 1608 (0603); Технология монтажа: SMT; Изготовитель: АО "НПО "ЭРКОН"
footprint КИК-1608_Зл (Катушка индуктивности с керамическим сердечником  типоразмер 1005(0402))
pins: 1, 2

## КИК-1608-10 нГн ±5% O
designator L?, comment 10 нГн ±5%  (value not drawn)
Катушка индуктивности с керамическим сердечником и  финишным покрытием контактных площадок оловом; Номиналиная индуктивность: 10 нГн; Добротность, не менее: 30; Резонансная частота, не менее: 4.80 ГГц; Сопротивление обмотки постоянноми току, не более: 0.130 Ом; Допустимый ток обмотки: 700 мА; Диапазон рабочих температур: от -60 до +125 ℃; Упаковка: Катушка и лента; Типоразмер: 1608 (0603); Технология монтажа: SMT; Изготовитель: АО "НПО "ЭРКОН"
footprint КИК-1608_О (Катушка индуктивности с керамическим сердечником  типоразмер 1005(0402))
pins: 1, 2

## КИК-1608-10 нГн ±5% Зл
designator L?, comment 10 нГн ±5%  (value not drawn)
Катушка индуктивности с керамическим сердечником и золотым покрытием контактных площадок; Номиналиная индуктивность: 10 нГн; Добротность, не менее: 30; Резонансная частота, не менее: 4.80 ГГц; Сопротивление обмотки постоянноми току, не более: 0.130 Ом; Допустимый ток обмотки: 700 мА; Диапазон рабочих температур: от -60 до +125 ℃; Упаковка: Катушка и лента; Типоразмер: 1608 (0603); Технология монтажа: SMT; Изготовитель: АО "НПО "ЭРКОН"
footprint КИК-1608_Зл (Катушка индуктивности с керамическим сердечником  типоразмер 1005(0402))
pins: 1, 2

## КИК-1608-10 нГн ±10% O
designator L?, comment 10 нГн ±10%  (value not drawn)
Катушка индуктивности с керамическим сердечником и  финишным покрытием контактных площадок оловом; Номиналиная индуктивность: 10 нГн; Добротность, не менее: 30; Резонансная частота, не менее: 4.80 ГГц; Сопротивление обмотки постоянноми току, не более: 0.130 Ом; Допустимый ток обмотки: 700 мА; Диапазон рабочих температур: от -60 до +125 ℃; Упаковка: Катушка и лента; Типоразмер: 1608 (0603); Технология монтажа: SMT; Изготовитель: АО "НПО "ЭРКОН"
footprint КИК-1608_О (Катушка индуктивности с керамическим сердечником  типоразмер 1005(0402))
pins: 1, 2

## КИК-1608-10 нГн ±10% Зл
designator L?, comment 10 нГн ±10%  (value not drawn)
Катушка индуктивности с керамическим сердечником и золотым покрытием контактных площадок; Номиналиная индуктивность: 10 нГн; Добротность, не менее: 30; Резонансная частота, не менее: 4.80 ГГц; Сопротивление обмотки постоянноми току, не более: 0.130 Ом; Допустимый ток обмотки: 700 мА; Диапазон рабочих температур: от -60 до +125 ℃; Упаковка: Катушка и лента; Типоразмер: 1608 (0603); Технология монтажа: SMT; Изготовитель: АО "НПО "ЭРКОН"
footprint КИК-1608_Зл (Катушка индуктивности с керамическим сердечником  типоразмер 1005(0402))
pins: 1, 2

## КИК-1608-11 нГн ±2% O
designator L?, comment 11 нГн ±2%  (value not drawn)
Катушка индуктивности с керамическим сердечником и  финишным покрытием контактных площадок оловом; Номиналиная индуктивность: 11 нГн; Добротность, не менее: 30; Резонансная частота, не менее: 4.00 ГГц; Сопротивление обмотки постоянноми току, не более: 0.130 Ом; Допустимый ток обмотки: 700 мА; Диапазон рабочих температур: от -60 до +125 ℃; Упаковка: Катушка и лента; Типоразмер: 1608 (0603); Технология монтажа: SMT; Изготовитель: АО "НПО "ЭРКОН"
footprint КИК-1608_О (Катушка индуктивности с керамическим сердечником  типоразмер 1005(0402))
pins: 1, 2

## КИК-1608-11 нГн ±2% Зл
designator L?, comment 11 нГн ±2%  (value not drawn)
Катушка индуктивности с керамическим сердечником и золотым покрытием контактных площадок; Номиналиная индуктивность: 11 нГн; Добротность, не менее: 30; Резонансная частота, не менее: 4.00 ГГц; Сопротивление обмотки постоянноми току, не более: 0.130 Ом; Допустимый ток обмотки: 700 мА; Диапазон рабочих температур: от -60 до +125 ℃; Упаковка: Катушка и лента; Типоразмер: 1608 (0603); Технология монтажа: SMT; Изготовитель: АО "НПО "ЭРКОН"
footprint КИК-1608_Зл (Катушка индуктивности с керамическим сердечником  типоразмер 1005(0402))
pins: 1, 2

## КИК-1608-11 нГн ±5% O
designator L?, comment 11 нГн ±5%  (value not drawn)
Катушка индуктивности с керамическим сердечником и  финишным покрытием контактных площадок оловом; Номиналиная индуктивность: 11 нГн; Добротность, не менее: 30; Резонансная частота, не менее: 4.00 ГГц; Сопротивление обмотки постоянноми току, не более: 0.130 Ом; Допустимый ток обмотки: 700 мА; Диапазон рабочих температур: от -60 до +125 ℃; Упаковка: Катушка и лента; Типоразмер: 1608 (0603); Технология монтажа: SMT; Изготовитель: АО "НПО "ЭРКОН"
footprint КИК-1608_О (Катушка индуктивности с керамическим сердечником  типоразмер 1005(0402))
pins: 1, 2

## КИК-1608-11 нГн ±5% Зл
designator L?, comment 11 нГн ±5%  (value not drawn)
Катушка индуктивности с керамическим сердечником и золотым покрытием контактных площадок; Номиналиная индуктивность: 11 нГн; Добротность, не менее: 30; Резонансная частота, не менее: 4.00 ГГц; Сопротивление обмотки постоянноми току, не более: 0.130 Ом; Допустимый ток обмотки: 700 мА; Диапазон рабочих температур: от -60 до +125 ℃; Упаковка: Катушка и лента; Типоразмер: 1608 (0603); Технология монтажа: SMT; Изготовитель: АО "НПО "ЭРКОН"
footprint КИК-1608_Зл (Катушка индуктивности с керамическим сердечником  типоразмер 1005(0402))
pins: 1, 2

## КИК-1608-11 нГн ±10% O
designator L?, comment 11 нГн ±10%  (value not drawn)
Катушка индуктивности с керамическим сердечником и  финишным покрытием контактных площадок оловом; Номиналиная индуктивность: 11 нГн; Добротность, не менее: 30; Резонансная частота, не менее: 4.00 ГГц; Сопротивление обмотки постоянноми току, не более: 0.130 Ом; Допустимый ток обмотки: 700 мА; Диапазон рабочих температур: от -60 до +125 ℃; Упаковка: Катушка и лента; Типоразмер: 1608 (0603); Технология монтажа: SMT; Изготовитель: АО "НПО "ЭРКОН"
footprint КИК-1608_О (Катушка индуктивности с керамическим сердечником  типоразмер 1005(0402))
pins: 1, 2

## КИК-1608-11 нГн ±10% Зл
designator L?, comment 11 нГн ±10%  (value not drawn)
Катушка индуктивности с керамическим сердечником и золотым покрытием контактных площадок; Номиналиная индуктивность: 11 нГн; Добротность, не менее: 30; Резонансная частота, не менее: 4.00 ГГц; Сопротивление обмотки постоянноми току, не более: 0.130 Ом; Допустимый ток обмотки: 700 мА; Диапазон рабочих температур: от -60 до +125 ℃; Упаковка: Катушка и лента; Типоразмер: 1608 (0603); Технология монтажа: SMT; Изготовитель: АО "НПО "ЭРКОН"
footprint КИК-1608_Зл (Катушка индуктивности с керамическим сердечником  типоразмер 1005(0402))
pins: 1, 2

## КИК-1608-12 нГн ±2% O
designator L?, comment 12 нГн ±2%  (value not drawn)
Катушка индуктивности с керамическим сердечником и  финишным покрытием контактных площадок оловом; Номиналиная индуктивность: 12 нГн; Добротность, не менее: 30; Резонансная частота, не менее: 4.00 ГГц; Сопротивление обмотки постоянноми току, не более: 0.130 Ом; Допустимый ток обмотки: 700 мА; Диапазон рабочих температур: от -60 до +125 ℃; Упаковка: Катушка и лента; Типоразмер: 1608 (0603); Технология монтажа: SMT; Изготовитель: АО "НПО "ЭРКОН"
footprint КИК-1608_О (Катушка индуктивности с керамическим сердечником  типоразмер 1005(0402))
pins: 1, 2

## КИК-1608-12 нГн ±2% Зл
designator L?, comment 12 нГн ±2%  (value not drawn)
Катушка индуктивности с керамическим сердечником и золотым покрытием контактных площадок; Номиналиная индуктивность: 12 нГн; Добротность, не менее: 30; Резонансная частота, не менее: 4.00 ГГц; Сопротивление обмотки постоянноми току, не более: 0.130 Ом; Допустимый ток обмотки: 700 мА; Диапазон рабочих температур: от -60 до +125 ℃; Упаковка: Катушка и лента; Типоразмер: 1608 (0603); Технология монтажа: SMT; Изготовитель: АО "НПО "ЭРКОН"
footprint КИК-1608_Зл (Катушка индуктивности с керамическим сердечником  типоразмер 1005(0402))
pins: 1, 2

## КИК-1608-12 нГн ±5% O
designator L?, comment 12 нГн ±5%  (value not drawn)
Катушка индуктивности с керамическим сердечником и  финишным покрытием контактных площадок оловом; Номиналиная индуктивность: 12 нГн; Добротность, не менее: 30; Резонансная частота, не менее: 4.00 ГГц; Сопротивление обмотки постоянноми току, не более: 0.130 Ом; Допустимый ток обмотки: 700 мА; Диапазон рабочих температур: от -60 до +125 ℃; Упаковка: Катушка и лента; Типоразмер: 1608 (0603); Технология монтажа: SMT; Изготовитель: АО "НПО "ЭРКОН"
footprint КИК-1608_О (Катушка индуктивности с керамическим сердечником  типоразмер 1005(0402))
pins: 1, 2

## КИК-1608-12 нГн ±5% Зл
designator L?, comment 12 нГн ±5%  (value not drawn)
Катушка индуктивности с керамическим сердечником и золотым покрытием контактных площадок; Номиналиная индуктивность: 12 нГн; Добротность, не менее: 30; Резонансная частота, не менее: 4.00 ГГц; Сопротивление обмотки постоянноми току, не более: 0.130 Ом; Допустимый ток обмотки: 700 мА; Диапазон рабочих температур: от -60 до +125 ℃; Упаковка: Катушка и лента; Типоразмер: 1608 (0603); Технология монтажа: SMT; Изготовитель: АО "НПО "ЭРКОН"
footprint КИК-1608_Зл (Катушка индуктивности с керамическим сердечником  типоразмер 1005(0402))
pins: 1, 2

## КИК-1608-12 нГн ±10% O
designator L?, comment 12 нГн ±10%  (value not drawn)
Катушка индуктивности с керамическим сердечником и  финишным покрытием контактных площадок оловом; Номиналиная индуктивность: 12 нГн; Добротность, не менее: 30; Резонансная частота, не менее: 4.00 ГГц; Сопротивление обмотки постоянноми току, не более: 0.130 Ом; Допустимый ток обмотки: 700 мА; Диапазон рабочих температур: от -60 до +125 ℃; Упаковка: Катушка и лента; Типоразмер: 1608 (0603); Технология монтажа: SMT; Изготовитель: АО "НПО "ЭРКОН"
footprint КИК-1608_О (Катушка индуктивности с керамическим сердечником  типоразмер 1005(0402))
pins: 1, 2

## КИК-1608-12 нГн ±10% Зл
designator L?, comment 12 нГн ±10%  (value not drawn)
Катушка индуктивности с керамическим сердечником и золотым покрытием контактных площадок; Номиналиная индуктивность: 12 нГн; Добротность, не менее: 30; Резонансная частота, не менее: 4.00 ГГц; Сопротивление обмотки постоянноми току, не более: 0.130 Ом; Допустимый ток обмотки: 700 мА; Диапазон рабочих температур: от -60 до +125 ℃; Упаковка: Катушка и лента; Типоразмер: 1608 (0603); Технология монтажа: SMT; Изготовитель: АО "НПО "ЭРКОН"
footprint КИК-1608_Зл (Катушка индуктивности с керамическим сердечником  типоразмер 1005(0402))
pins: 1, 2

## КИК-1608-15 нГн ±2% O
designator L?, comment 15 нГн ±2%  (value not drawn)
Катушка индуктивности с керамическим сердечником и  финишным покрытием контактных площадок оловом; Номиналиная индуктивность: 12 нГн; Добротность, не менее: 30; Резонансная частота, не менее: 4.00 ГГц; Сопротивление обмотки постоянноми току, не более: 0.170 Ом; Допустимый ток обмотки: 700 мА; Диапазон рабочих температур: от -60 до +125 ℃; Упаковка: Катушка и лента; Типоразмер: 1608 (0603); Технология монтажа: SMT; Изготовитель: АО "НПО "ЭРКОН"
footprint КИК-1608_О (Катушка индуктивности с керамическим сердечником  типоразмер 1005(0402))
pins: 1, 2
